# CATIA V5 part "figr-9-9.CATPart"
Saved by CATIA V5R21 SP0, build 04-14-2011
Part number: Part1
Bounding box of the stored display mesh (mm): x -15.705 to 88.369, y 0 to 286.83, z -20.723 to 20.723
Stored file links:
  D:\CATIA V5R21 E-RESOURCES\CATIA-V5R21\catia-v5r21-prt\c09-catia-v5r20-prt\c09-catia-v5r21-figr-9-9.CATPart
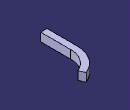
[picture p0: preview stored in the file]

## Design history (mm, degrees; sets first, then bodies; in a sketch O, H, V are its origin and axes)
Body1 (main body)
  Sketch1 on xy-plane, origin (0, 0, 0), H (1, 0, 0), V (0, 1, 0)
    line L1 (0, 0) -> (0, 150)
    arc A1 centre (131.8599, 150) radius 131.8599 from (0, 150) to (82.4884, 272.2681) cw
    length L1 = 150
    tangency: A1 L1
  Sketch2 on zx-plane, origin (0, 0, 0), H (-1, 0, 0), V (0, 0, 1)
    line L1 (15.7048, 20.7231) -> (15.7048, -20.7231)
    line L2 (15.7048, -20.7231) -> (-15.7048, -20.7231)
    line L3 (-15.7048, -20.7231) -> (-15.7048, 20.7231)
    line L4 (-15.7048, 20.7231) -> (15.7048, 20.7231)
    vertical: L1 V, L3 V
    horizontal: L2 H, L4 H
    equidistance: L1 L3 O, L2 L4 O
  Rib1: profile Sketch2, centre curve Sketch1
